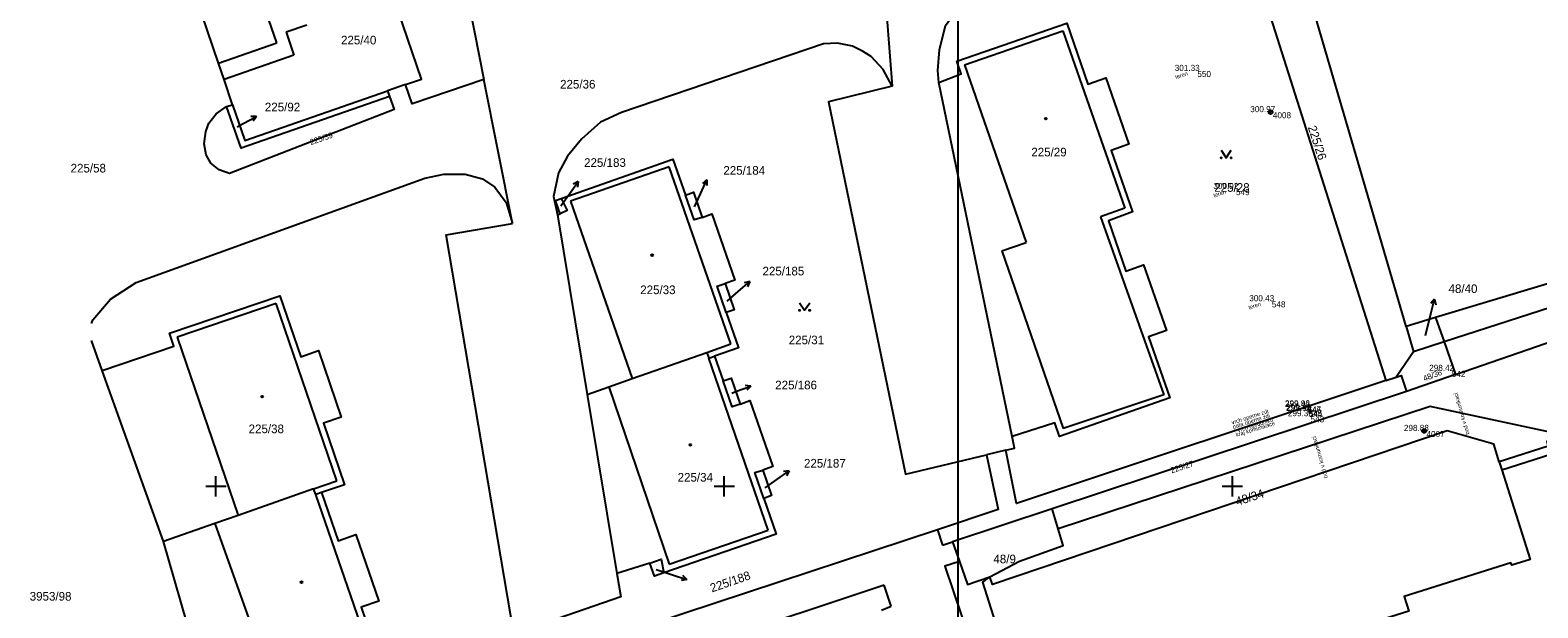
# Model space of a CAD drawing. Extents: x -599970 to -599524, y -1154772 to -1154457.
# Drawn here: x -599968.3 to -599820, y -1154661.9 to -1154605.1 of the extents above; entities that cross this region are included whole.
import ezdxf

# ---------------------------------------------------------------- set-up
doc = ezdxf.new("R2010")
doc.units = 0
for name, color, linetype in [('Z-KATASTRALNI MAPA', 7, 'Continuous'), ('Z-KRIZKY CTVERCOVE SITE', 7, 'Continuous'), ('Z-PEVNE BODY-CISLO', 7, 'Continuous'), ('Z-PEVNE BODY-VYSKA', 7, 'Continuous'), ('Z-PEVNE BODY-ZNACKA', 7, 'Continuous'), ('Z-PODROBNE BODY', 7, 'Continuous'), ('Z-PODROBNE BODY-CISLO', 7, 'Continuous'), ('Z-PODROBNE BODY-VYSKA', 7, 'Continuous'), ('Z-POPISY OBJEKTU A ZPEVNENYCH PLOCH', 7, 'Continuous'), ('Z-RAM ROZPISKA', 7, 'Continuous')]:
    doc.layers.add(name, color=color, linetype=linetype)

msp = doc.modelspace()

# ---------------------------------------------------------------- linework, layer by layer
at = {"layer": 'Z-KATASTRALNI MAPA'}
for p, q in [((-599849.84, -1154592.53), (-599834.91, -1154639.59)), ((-599884.59, -1154596.46), (-599883.46, -1154610.65)), ((-599832.92, -1154634.27), (-599842.8, -1154600.57)), ((-599944.01, -1154606.41), (-599945.3, -1154602.64)), ((-599941.05, -1154604.67), (-599943.07, -1154605.36)), ((-599943.07, -1154605.36), (-599942.32, -1154607.62)), ((-599876.37, -1154608.57), (-599866.68, -1154605.21)), ((-599866.68, -1154605.21), (-599860.6, -1154622.65)), ((-599949.75, -1154608.38), (-599944.01, -1154606.41)), ((-599942.32, -1154607.62), (-599949.17, -1154610.01)), ((-599876.37, -1154608.57), (-599870.28, -1154626.01)), ((-599920.83, -1154624.14), (-599923.65, -1154610.01)), ((-599871.68, -1154645.11), (-599878.9, -1154610.29)), ((-599931.35, -1154610.5), (-599933.11, -1154611.12)), ((-599933.11, -1154611.12), (-599932.91, -1154611.68)), ((-599948.94, -1154612.66), (-599948.36, -1154612.48)), ((-599947.89, -1154614.64), (-599947.32, -1154614.33)), ((-599947.32, -1154614.33), (-599945.99, -1154613.63)), ((-599945.99, -1154613.63), (-599946.56, -1154613.64)), ((-599945.99, -1154613.63), (-599946.32, -1154614.08)), ((-599905.41, -1154618.58), (-599915.11, -1154621.97)), ((-599899.36, -1154635.99), (-599905.41, -1154618.58)), ((-599915.23, -1154621.24), (-599914.35, -1154620.03)), ((-599914.35, -1154620.03), (-599914.84, -1154620.28)), ((-599914.35, -1154620.03), (-599914.44, -1154620.58)), ((-599902.34, -1154621.23), (-599901.71, -1154619.87)), ((-599901.71, -1154619.87), (-599902.14, -1154620.22)), ((-599901.71, -1154619.87), (-599901.69, -1154620.43)), ((-599916.08, -1154622.42), (-599915.23, -1154621.24)), ((-599915.11, -1154621.97), (-599909.05, -1154639.38)), ((-599902.93, -1154622.51), (-599902.34, -1154621.23)), ((-599916.4, -1154623.29), (-599916.12, -1154623.2)), ((-599916.4, -1154623.29), (-599913.47, -1154640.97)), ((-599860.6, -1154622.65), (-599862.98, -1154623.5)), ((-599862.98, -1154623.5), (-599856.74, -1154641.01)), ((-599872.68, -1154626.84), (-599870.28, -1154626.01)), ((-599828.05, -1154639.01), (-599791.7, -1154626.34)), ((-599872.68, -1154626.84), (-599866.65, -1154644.31)), ((-599899.71, -1154631.78), (-599898.61, -1154630.84)), ((-599898.61, -1154630.84), (-599897.48, -1154629.86)), ((-599897.48, -1154629.86), (-599898.02, -1154630)), ((-599897.48, -1154629.86), (-599897.69, -1154630.37)), ((-599944.08, -1154632.02), (-599953.79, -1154635.33)), ((-599938.11, -1154649.45), (-599944.08, -1154632.02)), ((-599830.49, -1154633.05), (-599830.13, -1154631.59)), ((-599830.13, -1154631.59), (-599830.49, -1154632.02)), ((-599830.13, -1154631.59), (-599830.01, -1154632.14)), ((-599830.02, -1154633.4), (-599832.92, -1154634.27)), ((-599831.02, -1154635.16), (-599830.49, -1154633.05)), ((-599830.02, -1154633.4), (-599829.18, -1154635.8)), ((-599953.79, -1154635.33), (-599947.81, -1154652.85)), ((-599832.92, -1154634.27), (-599832.19, -1154636.77)), ((-599901.7, -1154636.83), (-599899.36, -1154635.99)), ((-599832.19, -1154636.77), (-599833.89, -1154639.25)), ((-599829.18, -1154635.8), (-599832.19, -1154636.77)), ((-599829.18, -1154635.8), (-599828.05, -1154639.01)), ((-599895.67, -1154654.31), (-599901.5, -1154637.4)), ((-599900.94, -1154637.2), (-599900.1, -1154639.63)), ((-599955.15, -1154655.41), (-599961.19, -1154638.6)), ((-599834.91, -1154639.59), (-599833.89, -1154639.25)), ((-599828.05, -1154639.01), (-599832.9, -1154640.67)), ((-599913.47, -1154640.97), (-599910.57, -1154658.56)), ((-599911.36, -1154640.22), (-599905.41, -1154657.66)), ((-599899.26, -1154640.82), (-599898.79, -1154640.65)), ((-599898.79, -1154640.65), (-599897.38, -1154640.14)), ((-599897.38, -1154640.14), (-599897.94, -1154640.07)), ((-599897.38, -1154640.14), (-599897.77, -1154640.54)), ((-599832.9, -1154640.67), (-599867.73, -1154652.2)), ((-599856.74, -1154641.01), (-599866.65, -1154644.31)), ((-599872.29, -1154646.44), (-599874.19, -1154646.9)), ((-599823.51, -1154648.36), (-599818.69, -1154646.84)), ((-599894.83, -1154649.33), (-599893.6, -1154648.47)), ((-599893.6, -1154648.47), (-599894.15, -1154648.55)), ((-599893.6, -1154648.47), (-599893.87, -1154648.96)), ((-599940.38, -1154650.23), (-599938.11, -1154649.45)), ((-599895.98, -1154650.14), (-599894.83, -1154649.33)), ((-599934.32, -1154667.72), (-599940.18, -1154650.81)), ((-599867.73, -1154652.2), (-599877.55, -1154655.45)), ((-599867.14, -1154654.18), (-599867.73, -1154652.2)), ((-599950.09, -1154653.66), (-599943.86, -1154671.15)), ((-599905.41, -1154657.66), (-599895.67, -1154654.31)), ((-599879.03, -1154654.26), (-599878.52, -1154655.77)), ((-599950.53, -1154671.34), (-599955.15, -1154655.41)), ((-599878.52, -1154655.77), (-599877.55, -1154655.45)), ((-599877.55, -1154655.45), (-599876.86, -1154657.38)), ((-599907.31, -1154657.55), (-599910.57, -1154658.56)), ((-599906.69, -1154658.18), (-599905.09, -1154658.69)), ((-599905.09, -1154658.69), (-599903.66, -1154659.15)), ((-599903.66, -1154659.15), (-599904.22, -1154659.24)), ((-599903.66, -1154659.15), (-599904.06, -1154658.76)), ((-599884.26, -1154659.72), (-599911.05, -1154668.58)), ((-599883.56, -1154661.76), (-599884.26, -1154659.72)), ((-599884.54, -1154662.16), (-599883.56, -1154661.76))]:
    msp.add_line(p, q, dxfattribs=at)
for points in [[(-599927.46, -1154583.33), (-599926.29, -1154588.8), (-599927.77, -1154589.03), (-599923.65, -1154610.01)], [(-599931.35, -1154610.5), (-599929.78, -1154609.96), (-599935.72, -1154592.56), (-599937.52, -1154593.19)], [(-599878.9, -1154610.29), (-599879, -1154609.13), (-599878.82, -1154607.08), (-599878.24, -1154604.7), (-599877.23, -1154603.32), (-599876.28, -1154602.31), (-599874.9, -1154601.21), (-599849.84, -1154592.53)], [(-599948.36, -1154612.48), (-599949.17, -1154610.01), (-599949.75, -1154608.38), (-599953.06, -1154598.64)], [(-599878.9, -1154610.29), (-599876.7, -1154609.45), (-599877.13, -1154608.21), (-599866.31, -1154604.46), (-599864.22, -1154610.45), (-599862.47, -1154609.84), (-599860.2, -1154616.36), (-599861.95, -1154616.97), (-599859.83, -1154623.02), (-599862.21, -1154623.88), (-599860.49, -1154628.83), (-599858.74, -1154628.22), (-599856.5, -1154634.69), (-599858.25, -1154635.3), (-599856.16, -1154641.3), (-599867.01, -1154645.08), (-599867.47, -1154643.76), (-599871.68, -1154645.11)], [(-599883.46, -1154610.65), (-599884.35, -1154609.03), (-599885.55, -1154607.74), (-599886.4, -1154607.2), (-599887.39, -1154606.71), (-599888.86, -1154606.43), (-599890.22, -1154606.5), (-599910.1, -1154613.25), (-599912.17, -1154614.21), (-599914.04, -1154615.86), (-599915.4, -1154617.52), (-599916.3, -1154619.17), (-599916.78, -1154621.51), (-599916.4, -1154623.29)], [(-599923.65, -1154610.01), (-599930.7, -1154612.39), (-599931.35, -1154610.5)], [(-599932.91, -1154611.68), (-599932.47, -1154612.94), (-599948.67, -1154619.24), (-599949.69, -1154618.89), (-599950.48, -1154618.24), (-599950.94, -1154617.4), (-599951.14, -1154616.31), (-599950.98, -1154615.1), (-599950.7, -1154614.29), (-599949.98, -1154613.39), (-599948.94, -1154612.66)], [(-599932.91, -1154611.68), (-599947.5, -1154616.76), (-599948.94, -1154612.66)], [(-599948.36, -1154612.48), (-599947.14, -1154616), (-599933.11, -1154611.12)], [(-599883.46, -1154610.65), (-599889.74, -1154612.19), (-599882.18, -1154648.81), (-599874.19, -1154646.9)], [(-599851.12, -1154616.95), (-599850.62, -1154617.7), (-599850.12, -1154616.95)], [(-599916.02, -1154621.7), (-599905.04, -1154617.82), (-599903.81, -1154621.37)], [(-599962.24, -1154633.97), (-599962.09, -1154633.63), (-599960.35, -1154631.61), (-599957.85, -1154629.96), (-599929.46, -1154619.69), (-599927.57, -1154619.3), (-599925.49, -1154619.32), (-599923.77, -1154619.77), (-599922.56, -1154620.58), (-599921.43, -1154622.08), (-599920.83, -1154624.14)], [(-599782.89, -1154620.22), (-599786.61, -1154620.37), (-599830.02, -1154633.4)], [(-599916.12, -1154623.2), (-599916.59, -1154621.9), (-599916.02, -1154621.7)], [(-599916.02, -1154621.7), (-599915.43, -1154622.88), (-599916.12, -1154623.2)], [(-599903.81, -1154621.37), (-599903.02, -1154621.09), (-599902.16, -1154623.57)], [(-599902.16, -1154623.57), (-599902.96, -1154623.81), (-599903.81, -1154621.37)], [(-599902.16, -1154623.57), (-599901.21, -1154623.2), (-599898.96, -1154629.71), (-599899.9, -1154630.07)], [(-599910.57, -1154658.56), (-599910.18, -1154660.87), (-599920.69, -1154664.5), (-599927.36, -1154625.26), (-599920.83, -1154624.14)], [(-599791.7, -1154626.34), (-599792.42, -1154623.92), (-599829.18, -1154635.8)], [(-599899.79, -1154632.91), (-599900.7, -1154630.31), (-599899.9, -1154630.07)], [(-599899.9, -1154630.07), (-599899.01, -1154632.64), (-599899.79, -1154632.91)], [(-599961.19, -1154638.6), (-599954.12, -1154636.2), (-599954.55, -1154634.95), (-599943.7, -1154631.26), (-599941.65, -1154637.25), (-599939.92, -1154636.65), (-599937.67, -1154643.18), (-599939.42, -1154643.78), (-599937.35, -1154649.83), (-599939.62, -1154650.61)], [(-599892.59, -1154631.94), (-599892.09, -1154632.69), (-599891.59, -1154631.94)], [(-599899.79, -1154632.91), (-599898.59, -1154636.37), (-599900.94, -1154637.2)], [(-599961.19, -1154638.6), (-599962.24, -1154635.67)], [(-599913.47, -1154640.97), (-599911.36, -1154640.22), (-599909.05, -1154639.38), (-599901.7, -1154636.83), (-599901.5, -1154637.4), (-599900.94, -1154637.2)], [(-599900.1, -1154639.63), (-599899.32, -1154639.36), (-599898.43, -1154641.93)], [(-599898.43, -1154641.93), (-599899.23, -1154642.17), (-599900.1, -1154639.63)], [(-599834.91, -1154639.59), (-599871.25, -1154651.67), (-599872.29, -1154646.44)], [(-599833.89, -1154639.25), (-599833.4, -1154639.09), (-599832.9, -1154640.67)], [(-599898.43, -1154641.93), (-599897.47, -1154641.56), (-599895.23, -1154648.05), (-599896.19, -1154648.42)], [(-599813.46, -1154643.34), (-599818.16, -1154644.81), (-599830.56, -1154642.16), (-599867.14, -1154654.18)], [(-599813.46, -1154643.34), (-599812.94, -1154645.02), (-599813.7, -1154645.26), (-599814.09, -1154644.05), (-599816.15, -1154644.74), (-599815.77, -1154645.92), (-599817.04, -1154646.32), (-599817.45, -1154645.05), (-599819.09, -1154645.58), (-599818.95, -1154646.04), (-599823.76, -1154647.57)], [(-599823.76, -1154647.57), (-599824.3, -1154645.86), (-599828.88, -1154644.53), (-599873.61, -1154659.66), (-599873.87, -1154658.89)], [(-599872.29, -1154646.44), (-599871.44, -1154646.24), (-599871.68, -1154645.11)], [(-599874.19, -1154646.9), (-599873.05, -1154652.27), (-599879.03, -1154654.26)], [(-599896.11, -1154651.18), (-599896.98, -1154648.65), (-599896.19, -1154648.42)], [(-599896.19, -1154648.42), (-599895.33, -1154650.91), (-599896.11, -1154651.18)], [(-599823.76, -1154647.57), (-599823.51, -1154648.36), (-599820.72, -1154657.18), (-599822.53, -1154657.75), (-599822.61, -1154657.52), (-599833.11, -1154660.84), (-599832.67, -1154662.25), (-599838.58, -1154664.12), (-599834.28, -1154677.71), (-599833.78, -1154679.29), (-599820.75, -1154675.17), (-599819.44, -1154679.31)], [(-599939.62, -1154650.61), (-599940.18, -1154650.81), (-599940.38, -1154650.23), (-599947.81, -1154652.85), (-599950.09, -1154653.66), (-599955.15, -1154655.41)], [(-599939.62, -1154650.61), (-599937.98, -1154655.34), (-599936.22, -1154654.73), (-599933.96, -1154661.27), (-599935.72, -1154661.87), (-599933.56, -1154668.1), (-599944.42, -1154671.87), (-599944.85, -1154670.62), (-599950.53, -1154671.34)], [(-599896.11, -1154651.18), (-599894.9, -1154654.68), (-599905.93, -1154658.51)], [(-599879.03, -1154654.26), (-599944.63, -1154675.91), (-599945.27, -1154676.15)], [(-599873.87, -1154658.89), (-599870.95, -1154657.35), (-599866.65, -1154655.82), (-599867.14, -1154654.18)], [(-599907.31, -1154657.55), (-599906.21, -1154657.15), (-599905.93, -1154658.51)], [(-599905.93, -1154658.51), (-599906.87, -1154658.83), (-599907.31, -1154657.55)], [(-599876.86, -1154657.38), (-599878.31, -1154657.85), (-599875, -1154667.65)], [(-599876.86, -1154657.38), (-599876.05, -1154659.66), (-599873.87, -1154658.89)], [(-599869.54, -1154675.24), (-599874.55, -1154659.42), (-599873.87, -1154658.89)]]:
    msp.add_lwpolyline(points, dxfattribs=at)
for centre, radius in [((-599868.37, -1154613.85), 0.0875), ((-599851.12, -1154617.7), 0.05), ((-599850.12, -1154617.7), 0.05), ((-599907.08, -1154627.27), 0.0875), ((-599892.59, -1154632.69), 0.05), ((-599891.59, -1154632.69), 0.05), ((-599945.44, -1154641.18), 0.0875), ((-599903.33, -1154645.92), 0.0875), ((-599941.58, -1154659.42), 0.0875)]:
    msp.add_circle(centre, radius, dxfattribs=at)
at = {"layer": 'Z-KRIZKY CTVERCOVE SITE'}
for p, q in [((-599949, -1154650), (-599951, -1154650)), ((-599950, -1154651), (-599950, -1154649)), ((-599899, -1154650), (-599901, -1154650)), ((-599900, -1154651), (-599900, -1154649)), ((-599849, -1154650), (-599851, -1154650)), ((-599850, -1154651), (-599850, -1154649))]:
    msp.add_line(p, q, dxfattribs=at)
at = {"layer": 'Z-PEVNE BODY-ZNACKA'}
for centre, radius in [((-599846.25, -1154613.21), 0.188), ((-599846.25, -1154613.21), 0.188), ((-599846.25, -1154613.21), 0.00896), ((-599846.25, -1154613.21), 0.00896), ((-599831.14, -1154644.55), 0.188), ((-599831.14, -1154644.55), 0.188), ((-599831.14, -1154644.55), 0.00896), ((-599831.14, -1154644.55), 0.00896)]:
    msp.add_circle(centre, radius, dxfattribs=at)
at = {"layer": 'Z-PODROBNE BODY'}
for p, q in [((-599853.68, -1154609.16), (-599853.68, -1154609.16)), ((-599849.88, -1154620.77), (-599849.88, -1154620.77)), ((-599846.35, -1154631.8), (-599846.35, -1154631.8)), ((-599828.65, -1154638.64), (-599828.65, -1154638.64)), ((-599842.84, -1154642.13), (-599842.84, -1154642.13)), ((-599842.83, -1154642.18), (-599842.83, -1154642.18)), ((-599842.74, -1154642.52), (-599842.74, -1154642.52)), ((-599842.71, -1154642.58), (-599842.71, -1154642.58)), ((-599842.55, -1154643.1), (-599842.55, -1154643.1))]:
    msp.add_line(p, q, dxfattribs=at)
at = {"layer": 'Z-RAM ROZPISKA'}
msp.add_lwpolyline([(-599876.98, -1154456.65), (-599579.98, -1154456.65), (-599579.98, -1154771.65), (-599876.98, -1154771.65)], close=True, dxfattribs=at)

# ---------------------------------------------------------------- texts
at = {"layer": 'Z-KATASTRALNI MAPA'}
for s, p in [('225/40', (-599937.69, -1154606.55)), ('225/36', (-599916.14, -1154610.89)), ('225/92', (-599945.18, -1154613.13)), ('225/183', (-599913.78, -1154618.59)), ('225/29', (-599869.79, -1154617.56)), ('225/58', (-599964.29, -1154619.14)), ('225/184', (-599900.08, -1154619.36)), ('225/28', (-599851.79, -1154621.04)), ('225/185', (-599896.23, -1154629.26)), ('225/33', (-599908.26, -1154631.1)), ('48/40', (-599828.75, -1154630.99)), ('225/31', (-599893.65, -1154636.03)), ('225/186', (-599894.98, -1154640.46)), ('225/38', (-599946.78, -1154644.77)), ('225/187', (-599892.15, -1154648.15)), ('225/34', (-599904.58, -1154649.53)), ('48/9', (-599873.52, -1154657.56)), ('3953/98', (-599968.31, -1154661.23))]:
    msp.add_text(s, height=0.85, dxfattribs=at).set_placement(p)
for s, height, rotation, p in [('225/26', 0.85, 288, (-599842.6, -1154614.69)), ('225/39', 0.57, 19, (-599940.64, -1154616.45)), ('48/36', 0.57, 21, (-599831.12, -1154639.69)), ('225/27', 0.57, 18, (-599855.99, -1154648.72)), ('48/34', 0.85, 18, (-599849.53, -1154651.92)), ('225/188', 0.85, 19, (-599901.21, -1154660.43))]:
    msp.add_text(s, height=height, rotation=rotation, dxfattribs=at).set_placement(p)
at = {"layer": 'Z-PEVNE BODY-CISLO'}
for s, p in [(' 4008', (-599846.25, -1154613.81)), (' 4007', (-599831.14, -1154645.15))]:
    msp.add_text(s, height=0.6, dxfattribs=at).set_placement(p)
at = {"layer": 'Z-PEVNE BODY-VYSKA'}
for s, p in [('300.97 ', (-599848.25, -1154613.21)), ('298.88 ', (-599833.14, -1154644.55))]:
    msp.add_text(s, height=0.6, dxfattribs=at).set_placement(p)
at = {"layer": 'Z-PODROBNE BODY-CISLO'}
for s, p in [(' 550', (-599853.68, -1154609.76)), (' 549', (-599849.88, -1154621.37)), (' 548', (-599846.35, -1154632.4)), (' 542', (-599828.65, -1154639.24)), (' 547', (-599842.84, -1154642.73)), (' 546', (-599842.83, -1154642.78)), (' 545', (-599842.74, -1154643.12)), (' 544', (-599842.71, -1154643.18)), (' 543', (-599842.55, -1154643.7))]:
    msp.add_text(s, height=0.6, dxfattribs=at).set_placement(p)
at = {"layer": 'Z-PODROBNE BODY-VYSKA'}
for s, p in [('301.33 ', (-599855.68, -1154609.16)), ('300.92 ', (-599851.88, -1154620.77)), ('300.43 ', (-599848.35, -1154631.8)), ('298.42 ', (-599830.65, -1154638.64)), ('299.96 ', (-599844.84, -1154642.13)), ('299.42 ', (-599844.83, -1154642.18)), ('299.43 ', (-599844.74, -1154642.52)), ('299.30 ', (-599844.71, -1154642.58)), ('299.30 ', (-599844.55, -1154643.1))]:
    msp.add_text(s, height=0.6, dxfattribs=at).set_placement(p)
at = {"layer": 'Z-POPISY OBJEKTU A ZPEVNENYCH PLOCH'}
for s, rotation, p in [('teren', 17.9246, (-599855.56, -1154609.96)), ('teren', 17.9246, (-599851.81, -1154621.6)), ('teren', 17.9246, (-599848.36, -1154632.62)), ('bod v komunikaci', 106.301, (-599826.68, -1154644.85)), ('vrch operne zdi', 17.9246, (-599850.02, -1154643.93)), ('pata operne zdi', 17.9246, (-599849.91, -1154644.36)), ('kraj komunikace', 17.135, (-599849.6, -1154645.13)), ('vrch obrubniku', 17.9246, (-599849.42, -1154644.71)), ('bod v komunikaci', 106.301, (-599840.62, -1154649.13))]:
    msp.add_text(s, height=0.4, rotation=rotation, dxfattribs=at).set_placement(p)

doc.saveas('drawing.dxf')
